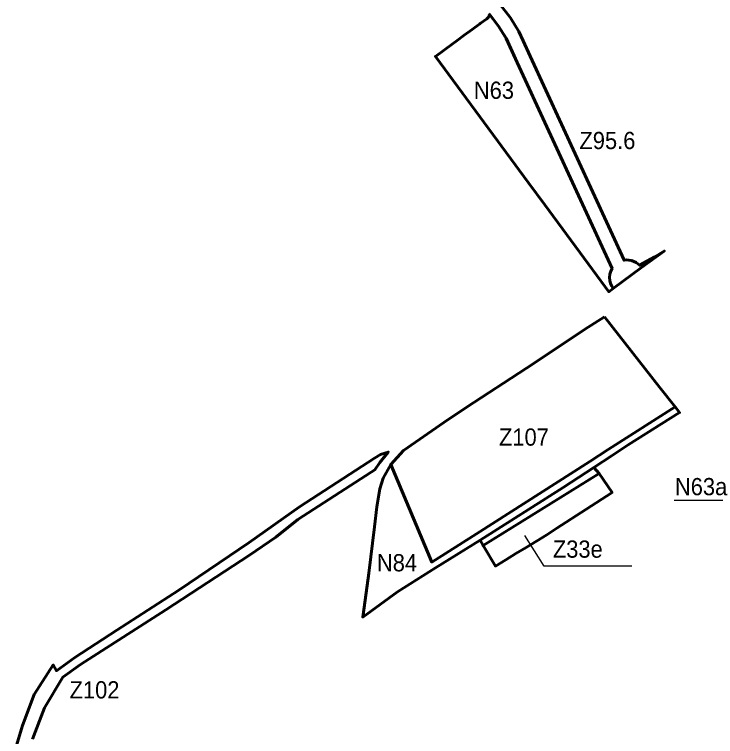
# Model space of a CAD drawing. Extents: x -650277 to -643422, y -1073980 to -1066720.
# Drawn here: x -648444 to -647467, y -1072626 to -1071620 of the extents above; entities that cross this region are included whole.
import ezdxf

# ---------------------------------------------------------------- set-up
doc = ezdxf.new("R2010")
doc.units = 0
doc.header["$LTSCALE"] = 9.6
for name, color, linetype, lineweight in [('15', 7, 'Continuous', 60), ('34', 7, 'Continuous', 60), ('42', 7, 'Continuous', 60), ('45', 7, 'Continuous', 60), ('60', 7, 'Continuous', 60), ('63', 7, 'Continuous', 25), ('8', 7, 'Continuous', 60)]:
    doc.layers.add(name, color=color, linetype=linetype, lineweight=lineweight)

msp = doc.modelspace()

# ---------------------------------------------------------------- linework, layer by layer
at = {"layer": '15'}
msp.add_lwpolyline([(-647795.4, -1072352.415), (-647679.66, -1072279.15), (-647637.082, -1072251.377), (-647629.67, -1072259.82), (-647791.198, -1072360.119)], close=True, dxfattribs=at)
at = {"layer": '34'}
for points in [[(-647621.97, -1072041.73), (-647649.76, -1072059.06), (-647683.63, -1072081.94), (-647730.53, -1072112.84), (-647814.58, -1072167.67), (-647845.58, -1072188.94), (-647901.91, -1072227.6), (-647919.68, -1072247.09), (-647862.615, -1072383.084)], [(-647523.71, -1072167.071), (-647545.44, -1072139.35), (-647621.97, -1072041.73)], [(-647862.615, -1072383.084), (-647800.2, -1072343.615), (-647642.504, -1072242.974), (-647616.719, -1072226.154), (-647523.71, -1072167.071)]]:
    msp.add_lwpolyline(points, dxfattribs=at)
at = {"layer": '42'}
for points in [[(-647637.082, -1072251.377), (-647611.306, -1072234.563), (-647589.02, -1072219.66), (-647517.51, -1072174.98), (-647523.71, -1072167.071), (-647616.719, -1072226.154), (-647642.504, -1072242.974), (-647800.2, -1072343.615)], [(-647800.2, -1072343.615), (-647862.615, -1072383.084), (-647919.68, -1072247.09), (-647930.36, -1072266.38), (-647934.86, -1072280.99), (-647939.26, -1072306.1), (-647942.54, -1072333.82), (-647950.2, -1072398.61), (-647956.786, -1072446.511), (-647958.82, -1072459.74), (-647910.27, -1072424.51), (-647857.52, -1072391.14), (-647795.4, -1072352.415)], [(-647795.4, -1072352.415), (-647679.66, -1072279.15), (-647637.082, -1072251.377)]]:
    msp.add_lwpolyline(points, dxfattribs=at)
at = {"layer": '45'}
msp.add_lwpolyline([(-647817.33, -1071649.51), (-647806.35, -1071641.47), (-647795.76, -1071633.72), (-647794.98, -1071633.15), (-647786.1, -1071626.65), (-647781.134, -1071621.645), (-647769.498, -1071636.647), (-647758.889, -1071653.742), (-647743.48, -1071687.426), (-647611.514, -1071974.086), (-647613.455, -1071978.031), (-647614.654, -1071982.238), (-647615.083, -1071986.65), (-647614.76, -1071990.762), (-647613.637, -1071995.081), (-647611.779, -1071999.069), (-647609.808, -1072001.962), (-647616.12, -1072006.7), (-647621.06, -1072000), (-647644.38, -1071968.3), (-647705.291, -1071885.501), (-647727.85, -1071854.86), (-647857.52, -1071678.92), (-647834.345, -1071661.969), (-647827.42, -1071656.89)], close=True, dxfattribs=at)
at = {"layer": '60'}
for points in [[(-647725.629, -1071678.373), (-647735.352, -1071657.117), (-647741.34, -1071644.028), (-647753.065, -1071625.201), (-647767.784, -1071606.225), (-647782.408, -1071590.847), (-647798.911, -1071576.526), (-647817.375, -1071563.458), (-647834.953, -1071553.406)], [(-647782.97, -1071619.278), (-647769.498, -1071636.647), (-647758.994, -1071653.513), (-647743.48, -1071687.426), (-647611.514, -1071974.086)], [(-647570.747, -1071972.644), (-647538.922, -1071950.099), (-647551.962, -1071958.049), (-647573.283, -1071969.627), (-647575.415, -1071967.709), (-647577.881, -1071965.979), (-647581.036, -1071964.346), (-647584.363, -1071963.196), (-647588.064, -1071962.51), (-647591.518, -1071962.387), (-647594.731, -1071962.714), (-647725.614, -1071678.405), (-647726.774, -1071675.885), (-647725.629, -1071678.373)], [(-647611.514, -1071974.086), (-647613.455, -1071978.031), (-647614.654, -1071982.238), (-647615.083, -1071986.65), (-647614.76, -1071990.762), (-647613.637, -1071995.081), (-647611.779, -1071999.069), (-647609.808, -1072001.962), (-647570.747, -1071972.644)], [(-648418.45, -1072629.91), (-648409.08, -1072604.25), (-648401.91, -1072586.1), (-648376.47, -1072543.52), (-648351.83, -1072525.81), (-648232.86, -1072449.45), (-648116.32, -1072373.44), (-648079.76, -1072348.46), (-648049.33, -1072323.77), (-647946.88, -1072257.82), (-647941.77, -1072254.45), (-647934.9, -1072244.55), (-647923.16, -1072229.85), (-647933.95, -1072233.18), (-647942.21, -1072238.54), (-648046.69, -1072306.3), (-648117.12, -1072356), (-648214.73, -1072422.41), (-648300.98, -1072478.1), (-648359.61, -1072515.85), (-648385.28, -1072534.41), (-648389.69, -1072526.36), (-648416.41, -1072567.43), (-648432.45, -1072610.56), (-648443.77, -1072648.02)]]:
    msp.add_lwpolyline(points, dxfattribs=at)
at = {"layer": '63'}
msp.add_line((-647525, -1072297), (-647387, -1072297), dxfattribs=at)
msp.add_lwpolyline([(-647584, -1072389), (-647706, -1072389), (-647733, -1072346)], dxfattribs=at)
at = {"layer": '8'}
msp.add_lwpolyline([(-647629.67, -1072259.82), (-647611.51, -1072286.26), (-647648.09, -1072309.95), (-647688.26, -1072336.06), (-647702.35, -1072345.14), (-647716.62, -1072353.95), (-647730.97, -1072362.6), (-647745.32, -1072371.26), (-647759.68, -1072379.91), (-647774.04, -1072388.57), (-647791.198, -1072360.119)], close=True, dxfattribs=at)

# ---------------------------------------------------------------- texts
at = {"layer": '63', "width": 0.95}
for s, p in [('N63', (-647804, -1071738)), ('Z95.6', (-647657, -1071808)), ('Z107', (-647769, -1072221)), ('N63a', (-647524, -1072290)), ('Z33e', (-647694, -1072377)), ('N84', (-647939, -1072396)), ('Z102', (-648367, -1072573))]:
    msp.add_text(s, height=24, dxfattribs=at).set_placement(p)

doc.saveas('drawing.dxf')
